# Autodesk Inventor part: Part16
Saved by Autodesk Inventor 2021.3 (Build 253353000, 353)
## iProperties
Created: 2023-09
Part Number: Part16
Material: Generic
Document SubType Name: Modeling
Designer: AdminForWorker
Density: 1 g/cm^3
Appearance: Default
Author: AdminForWorker
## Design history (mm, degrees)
feature "baseplate_top (7)" [Body]
feature "Body57"
feature "Body59"
feature "top_sensor_mount (2)" [Body]
feature "Body66"
feature "Body72"
feature "Body76"
feature "Body77"
feature "Body79"
body "Solid1"
body "Solid2"
body "Solid3"
body "Solid4"
body "Solid5"
body "Solid6"
body "Solid7"
body "Solid8"
body "Solid9"
